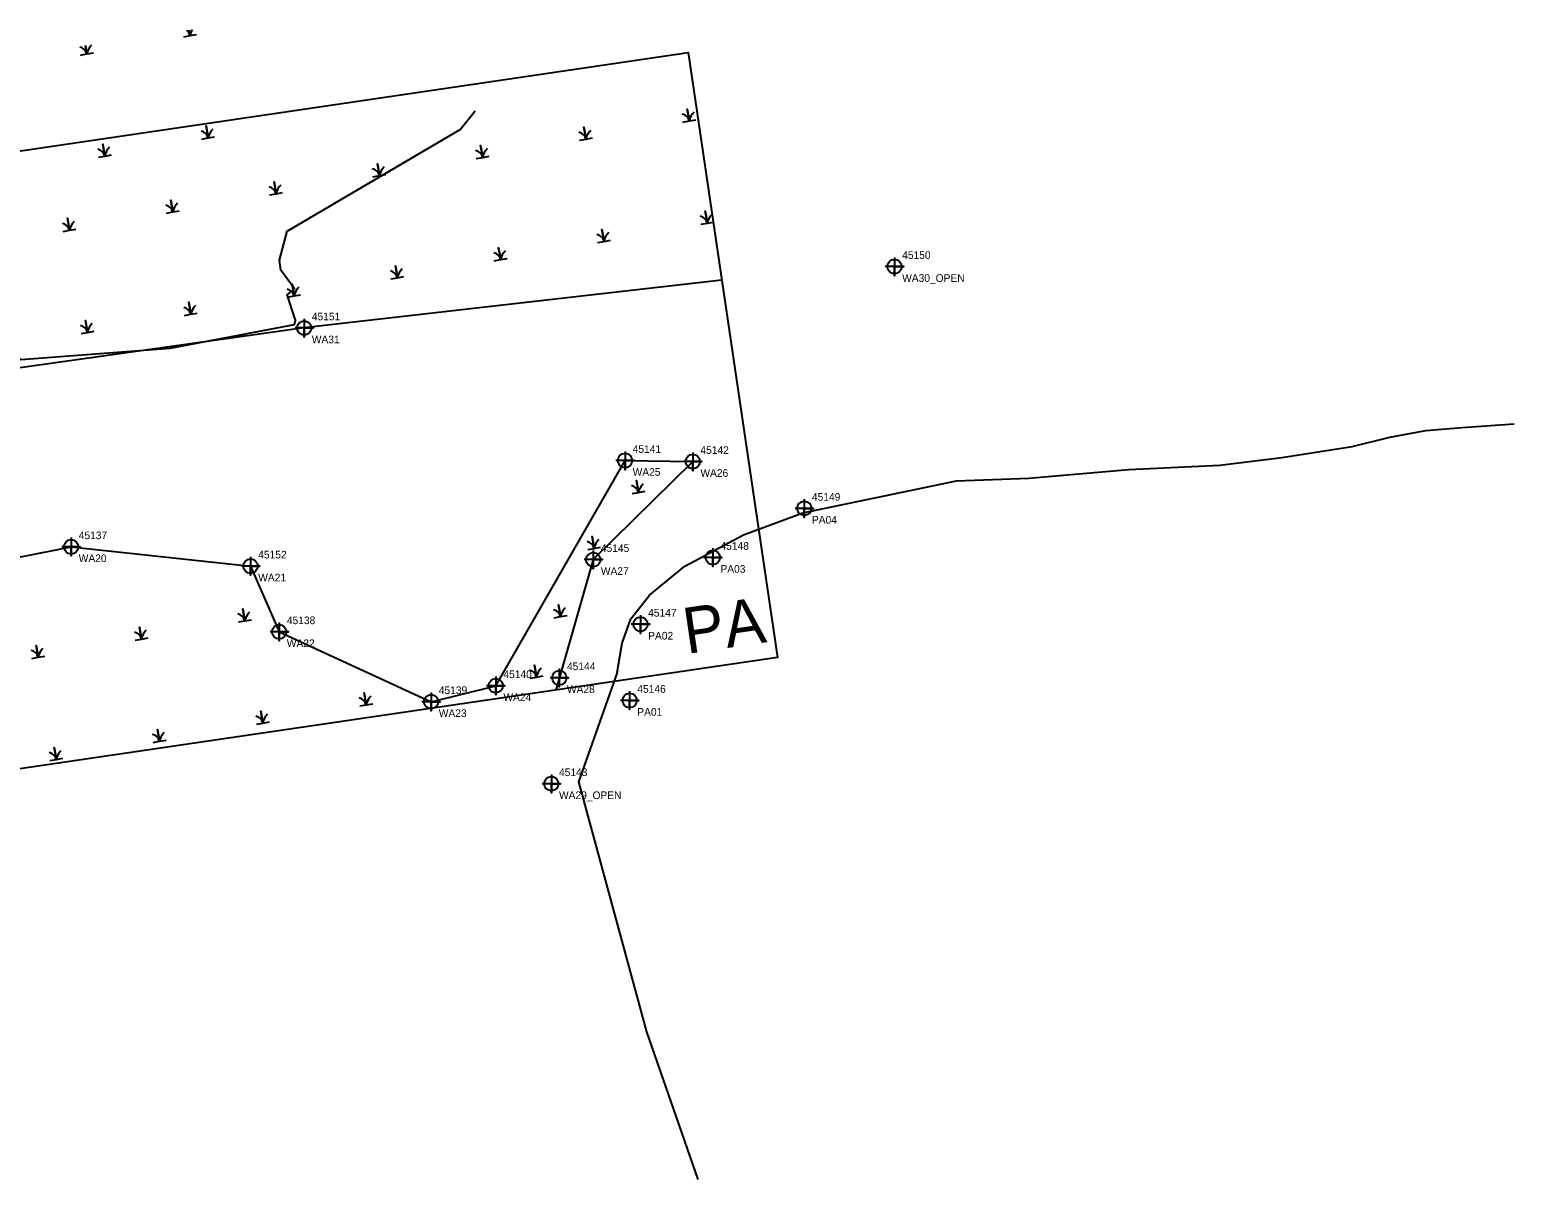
# Model space of a CAD drawing. Extents: x 2111078 to 2112839, y 581517 to 581907.
# Drawn here: x 2112353.6 to 2112839.1, y 581523.2 to 581906.7 of the extents above; entities that cross this region are included whole.
import ezdxf

# ---------------------------------------------------------------- set-up
doc = ezdxf.new("R2010")
doc.units = 0
for name, color, linetype in [('Default', 7, 'Continuous'), ('Exist Environmental Wetland Boundary', 7, 'Continuous'), ('Exist Environmental Wetland Boundary Cogo Comment', 7, 'Continuous'), ('Exist Environmental Wetland Boundary Cogo Number', 7, 'Continuous'), ('Exist Environmental Wetland Boundary Cogo Point CELL', 7, 'Continuous'), ('Exist Hydro Jurisdictional Stream or Body of Water Mitigable', 7, 'Continuous'), ('Exist Hydro Jurisdictional Stream or Body of Water Mitigable Cogo Comment', 7, 'Continuous'), ('Exist Hydro Jurisdictional Stream or Body of Water Mitigable Cogo Number', 7, 'Continuous'), ('Exist Hydro Jurisdictional Stream or Body of Water Mitigable Cogo Point CELL', 7, 'Continuous'), ('Exist Hydro Jurisdictional Stream or Body of Water Mitigable Text', 7, 'Continuous'), ('Exist Hydro Jurisdictional Stream or Body of Water NEU NonMitigable', 7, 'Continuous'), ('Exist Hydro Swamp or Marsh', 7, 'Continuous')]:
    doc.layers.add(name, color=color, linetype=linetype)

msp = doc.modelspace()

# ---------------------------------------------------------------- linework, layer by layer
at = {"layer": 'Default'}
msp.add_lwpolyline([(2111089.87, 581523.16), (2111077.52, 581722.78), (2111579.66, 581753.48), (2112568.99, 581899.18), (2112598.13, 581701.32), (2111600.4, 581554.74), (2111516.52, 581549.55)], close=True, dxfattribs=at)
at = {"layer": 'Exist Environmental Wetland Boundary'}
msp.add_lwpolyline([(2112579.95, 581824.73), (2112443.39, 581809.13), (2112256.64, 581782.86), (2112109, 581759.83), (2112105.64, 581760.42), (2112101.13, 581745.95), (2112105.09, 581733.68), (2112106.09, 581733.21), (2112105.61, 581730.22), (2112107.23, 581715.72), (2112118.04, 581694.33), (2112231.63, 581710.61), (2112367.17, 581737.55), (2112425.86, 581731.24), (2112435.22, 581709.75), (2112484.9, 581686.89), (2112506.03, 581692.11), (2112548.3, 581765.77), (2112570.44, 581765.42), (2112537.9, 581733.37), (2112525.65, 581690.67)], dxfattribs=at)
at = {"layer": 'Exist Environmental Wetland Boundary Cogo Point CELL'}
for points in [[(2112636.41, 581832.2), (2112636.41, 581826.2), (2112636.41, 581829.2), (2112639.41, 581829.2), (2112633.41, 581829.2)], [(2112443.39, 581812.12), (2112443.39, 581806.12), (2112443.39, 581809.12), (2112446.39, 581809.12), (2112440.39, 581809.12)], [(2112548.29, 581768.77), (2112548.29, 581762.77), (2112548.29, 581765.77), (2112551.29, 581765.77), (2112545.29, 581765.77)], [(2112570.44, 581768.42), (2112570.44, 581762.42), (2112570.44, 581765.42), (2112573.44, 581765.42), (2112567.44, 581765.42)], [(2112367.17, 581740.55), (2112367.17, 581734.55), (2112367.17, 581737.55), (2112370.17, 581737.55), (2112364.17, 581737.55)], [(2112425.86, 581734.24), (2112425.86, 581728.24), (2112425.86, 581731.24), (2112428.86, 581731.24), (2112422.86, 581731.24)], [(2112537.9, 581736.36), (2112537.9, 581730.36), (2112537.9, 581733.36), (2112540.9, 581733.36), (2112534.9, 581733.36)], [(2112435.22, 581712.75), (2112435.22, 581706.75), (2112435.22, 581709.75), (2112438.22, 581709.75), (2112432.22, 581709.75)], [(2112526.81, 581697.71), (2112526.81, 581691.71), (2112526.81, 581694.71), (2112529.81, 581694.71), (2112523.81, 581694.71)], [(2112506.03, 581695.11), (2112506.03, 581689.11), (2112506.03, 581692.11), (2112509.03, 581692.11), (2112503.03, 581692.11)], [(2112484.9, 581689.89), (2112484.9, 581683.89), (2112484.9, 581686.89), (2112487.9, 581686.89), (2112481.9, 581686.89)], [(2112524.21, 581663.06), (2112524.21, 581657.06), (2112524.21, 581660.06), (2112527.21, 581660.06), (2112521.21, 581660.06)]]:
    msp.add_lwpolyline(points, dxfattribs=at)
for centre in [(2112636.41, 581829.2), (2112443.39, 581809.12), (2112548.29, 581765.77), (2112570.44, 581765.42), (2112367.17, 581737.55), (2112425.86, 581731.24), (2112537.9, 581733.36), (2112435.22, 581709.75), (2112506.03, 581692.11), (2112526.81, 581694.71), (2112484.9, 581686.89), (2112524.21, 581660.06)]:
    msp.add_circle(centre, 2.34, dxfattribs=at)
at = {"layer": 'Exist Hydro Jurisdictional Stream or Body of Water Mitigable'}
msp.add_lwpolyline([(2112100.23, 581748.26), (2112103.02, 581756.15), (2112105.64, 581760.42), (2112110.13, 581763.39), (2112118.12, 581767.86), (2112152.81, 581774.25), (2112200.61, 581786.03), (2112247.18, 581789.46), (2112301.01, 581801.47), (2112342.46, 581803.44), (2112346.85, 581801.19), (2112350.69, 581798.8), (2112399.61, 581802.48), (2112440.25, 581810.21), (2112440.58, 581811.7), (2112437.79, 581819.92), (2112440.2, 581821.93), (2112435.76, 581827.98), (2112435.27, 581831.28), (2112437.88, 581840.73), (2112494.44, 581874.08), (2112499.34, 581880.11)], dxfattribs=at)
at = {"layer": 'Exist Hydro Jurisdictional Stream or Body of Water Mitigable Cogo Point CELL'}
for points in [[(2112606.91, 581753.13), (2112606.91, 581747.13), (2112606.91, 581750.13), (2112609.91, 581750.13), (2112603.91, 581750.13)], [(2112577, 581737.07), (2112577, 581731.07), (2112577, 581734.07), (2112580, 581734.07), (2112574, 581734.07)], [(2112553.36, 581715.22), (2112553.36, 581709.22), (2112553.36, 581712.22), (2112556.36, 581712.22), (2112550.36, 581712.22)], [(2112549.81, 581690.31), (2112549.81, 581684.31), (2112549.81, 581687.31), (2112552.81, 581687.31), (2112546.81, 581687.31)]]:
    msp.add_lwpolyline(points, dxfattribs=at)
for centre in [(2112606.91, 581750.13), (2112577, 581734.07), (2112553.36, 581712.22), (2112549.81, 581687.31)]:
    msp.add_circle(centre, 2.34, dxfattribs=at)
at = {"layer": 'Exist Hydro Jurisdictional Stream or Body of Water NEU NonMitigable'}
for points in [[(2112656.68, 581759.08), (2112680.36, 581759.96), (2112713.04, 581762.87), (2112742.82, 581764.2), (2112763.01, 581766.73), (2112786.04, 581770.35), (2112798.35, 581773.41), (2112810.13, 581775.61), (2112822.02, 581776.57), (2112839.07, 581777.8)], [(2112545.78, 581696.43), (2112547.4, 581706.04), (2112550.17, 581714.04), (2112556.31, 581721.74), (2112567.84, 581731.22), (2112587.06, 581741.49), (2112606.48, 581748.69), (2112656.68, 581759.08)], [(2112545.78, 581696.43), (2112533.1, 581660.7), (2112555.35, 581578.88), (2112572.1, 581530.62)]]:
    msp.add_lwpolyline(points, dxfattribs=at)
at = {"layer": 'Exist Hydro Swamp or Marsh'}
for p, q in [((2112552.43, 581757.08), (2112552.43, 581757.08)), ((2112537.9, 581738.78), (2112537.9, 581738.78)), ((2112526.92, 581716.49), (2112526.92, 581716.49)), ((2112519.08, 581696.72), (2112519.08, 581696.72))]:
    msp.add_line(p, q, dxfattribs=at)
for points in [[(2112403.99, 581904.35), (2112406.11, 581904.72), (2112405.79, 581906.52)], [(2112405.79, 581906.52), (2112406.11, 581904.72), (2112408.23, 581905.09)], [(2112370.21, 581898.39), (2112372.33, 581898.76), (2112371.85, 581901.52)], [(2112371.85, 581901.52), (2112372.33, 581898.76), (2112374.45, 581899.14)], [(2112567.22, 581876.46), (2112569.33, 581876.83), (2112568.65, 581880.72), (2112569.33, 581876.83), (2112571.45, 581877.21)], [(2112409.89, 581870.92), (2112412.01, 581871.29), (2112411.32, 581875.18), (2112412.01, 581871.29), (2112414.12, 581871.66)], [(2112533.44, 581870.5), (2112535.56, 581870.88), (2112534.87, 581874.76), (2112535.56, 581870.88), (2112537.67, 581871.25)], [(2112376.11, 581864.96), (2112378.23, 581865.33), (2112377.54, 581869.22), (2112378.23, 581865.33), (2112380.34, 581865.71)], [(2112499.66, 581864.55), (2112501.78, 581864.92), (2112501.09, 581868.81), (2112501.78, 581864.92), (2112503.89, 581865.29)], [(2112465.88, 581858.59), (2112468, 581858.96), (2112467.31, 581862.85), (2112468, 581858.96), (2112470.11, 581859.34)], [(2112432.1, 581852.64), (2112434.22, 581853.01), (2112433.53, 581856.89), (2112434.22, 581853.01), (2112436.33, 581853.38)], [(2112398.32, 581846.68), (2112400.44, 581847.05), (2112399.75, 581850.94), (2112400.44, 581847.05), (2112402.55, 581847.43)], [(2112364.54, 581840.72), (2112366.66, 581841.1), (2112365.97, 581844.98), (2112366.66, 581841.1), (2112368.77, 581841.47)], [(2112573.11, 581843.03), (2112575.23, 581843.4), (2112574.54, 581847.29), (2112575.23, 581843.4), (2112577.15, 581843.74)], [(2112539.33, 581837.07), (2112541.45, 581837.45), (2112540.76, 581841.33), (2112541.45, 581837.45), (2112543.57, 581837.82)], [(2112505.55, 581831.12), (2112507.67, 581831.49), (2112506.98, 581835.38), (2112507.67, 581831.49), (2112509.79, 581831.87)], [(2112471.77, 581825.16), (2112473.89, 581825.54), (2112473.21, 581829.42), (2112473.89, 581825.54), (2112476.01, 581825.91)], [(2112437.99, 581819.21), (2112440.11, 581819.58), (2112439.43, 581823.46), (2112440.11, 581819.58), (2112442.23, 581819.95)], [(2112404.21, 581813.25), (2112406.33, 581813.62), (2112405.65, 581817.51), (2112406.33, 581813.62), (2112408.45, 581814)], [(2112370.43, 581807.29), (2112372.55, 581807.67), (2112371.87, 581811.55), (2112372.55, 581807.67), (2112374.67, 581808.04)], [(2112550.62, 581754.95), (2112552.74, 581755.32), (2112552.05, 581759.21), (2112552.74, 581755.32), (2112554.85, 581755.7)], [(2112536.09, 581736.65), (2112538.21, 581737.03), (2112537.53, 581740.91), (2112538.21, 581737.03), (2112540.33, 581737.4)], [(2112421.9, 581712.96), (2112424.01, 581713.33), (2112423.33, 581717.22), (2112424.01, 581713.33), (2112426.13, 581713.71)], [(2112525.11, 581714.37), (2112527.23, 581714.74), (2112526.55, 581718.62), (2112527.23, 581714.74), (2112529.35, 581715.11)], [(2112388.12, 581707), (2112390.23, 581707.38), (2112389.55, 581711.26), (2112390.23, 581707.38), (2112392.35, 581707.75)], [(2112354.34, 581701.05), (2112356.45, 581701.42), (2112355.77, 581705.31), (2112356.45, 581701.42), (2112358.57, 581701.8)], [(2112517.27, 581694.59), (2112519.39, 581694.96), (2112518.7, 581698.85), (2112519.39, 581694.96), (2112521.5, 581695.34)], [(2112461.57, 581685.49), (2112463.69, 581685.86), (2112463, 581689.75), (2112463.69, 581685.86), (2112465.81, 581686.23)], [(2112427.79, 581679.53), (2112429.91, 581679.91), (2112429.22, 581683.79), (2112429.91, 581679.91), (2112432.03, 581680.28)], [(2112394.01, 581673.58), (2112396.13, 581673.95), (2112395.44, 581677.83), (2112396.13, 581673.95), (2112398.25, 581674.32)], [(2112360.23, 581667.62), (2112362.35, 581667.99), (2112361.66, 581671.88), (2112362.35, 581667.99), (2112364.47, 581668.37)]]:
    msp.add_lwpolyline(points, dxfattribs=at)
for centre, radius, start, end in [((2112410.87, 581904.02), 4.81, 146.4858, 171.6222), ((2112377.09, 581898.06), 4.81, 132.1274, 171.6222), ((2112403.13, 581903.97), 3.07, 14.1403, 52.2834), ((2112369.35, 581898.01), 3.07, 14.1403, 77.535), ((2112566.35, 581876.08), 3.07, 14.1403, 77.535), ((2112574.09, 581876.13), 4.81, 132.1274, 171.6222), ((2112409.02, 581870.54), 3.07, 14.1403, 77.535), ((2112416.76, 581870.59), 4.81, 132.1274, 171.6222), ((2112532.57, 581870.13), 3.07, 14.1403, 77.535), ((2112540.31, 581870.18), 4.81, 132.1274, 171.6222), ((2112382.98, 581864.63), 4.81, 132.1274, 171.6222), ((2112506.53, 581864.22), 4.81, 132.1274, 171.6222), ((2112375.24, 581864.58), 3.07, 14.1403, 77.535), ((2112498.79, 581864.17), 3.07, 14.1403, 77.535), ((2112465.01, 581858.21), 3.07, 14.1403, 77.535), ((2112472.75, 581858.26), 4.81, 132.1274, 171.6222), ((2112431.23, 581852.26), 3.07, 14.1403, 77.535), ((2112438.97, 581852.31), 4.81, 132.1274, 171.6222), ((2112397.45, 581846.3), 3.07, 14.1403, 77.535), ((2112405.19, 581846.35), 4.81, 132.1274, 171.6222), ((2112363.68, 581840.34), 3.07, 14.1403, 77.535), ((2112371.41, 581840.4), 4.81, 132.1274, 171.6222), ((2112572.25, 581842.65), 3.07, 14.1403, 77.535), ((2112579.98, 581842.7), 4.81, 132.1274, 171.6222), ((2112538.47, 581836.7), 3.07, 14.1403, 77.535), ((2112546.2, 581836.75), 4.81, 132.1274, 171.6222), ((2112504.69, 581830.74), 3.07, 14.1403, 77.535), ((2112512.42, 581830.79), 4.81, 132.1274, 171.6222), ((2112470.91, 581824.78), 3.07, 14.1403, 77.535), ((2112478.64, 581824.84), 4.81, 132.1274, 171.6222), ((2112437.13, 581818.83), 3.07, 14.1403, 77.535), ((2112444.86, 581818.88), 4.81, 132.1274, 171.6222), ((2112403.35, 581812.87), 3.07, 14.1403, 77.535), ((2112411.09, 581812.92), 4.81, 132.1274, 171.6222), ((2112369.57, 581806.92), 3.07, 14.1403, 77.535), ((2112377.31, 581806.97), 4.81, 132.1274, 171.6222), ((2112549.75, 581754.57), 3.07, 14.1403, 77.535), ((2112557.49, 581754.62), 4.81, 132.1274, 171.6222), ((2112535.23, 581736.28), 3.07, 14.1403, 77.535), ((2112542.97, 581736.33), 4.81, 132.1274, 171.6222), ((2112531.98, 581714.04), 4.81, 132.1274, 171.6222), ((2112421.03, 581712.58), 3.07, 14.1403, 77.535), ((2112428.77, 581712.63), 4.81, 132.1274, 171.6222), ((2112524.25, 581713.99), 3.07, 14.1403, 77.535), ((2112387.25, 581706.63), 3.07, 14.1403, 77.535), ((2112394.99, 581706.68), 4.81, 132.1274, 171.6222), ((2112353.47, 581700.67), 3.07, 14.1403, 77.535), ((2112361.21, 581700.72), 4.81, 132.1274, 171.6222), ((2112524.14, 581694.26), 4.81, 132.1274, 171.6222), ((2112516.4, 581694.21), 3.07, 14.1403, 77.535), ((2112460.71, 581685.11), 3.07, 14.1403, 77.535), ((2112468.44, 581685.16), 4.81, 132.1274, 171.6222), ((2112426.93, 581679.15), 3.07, 14.1403, 77.535), ((2112434.66, 581679.21), 4.81, 132.1274, 171.6222), ((2112393.15, 581673.2), 3.07, 14.1403, 77.535), ((2112400.88, 581673.25), 4.81, 132.1274, 171.6222), ((2112359.37, 581667.24), 3.07, 14.1403, 77.535), ((2112367.1, 581667.29), 4.81, 132.1274, 171.6222)]:
    msp.add_arc(centre, radius, start, end, dxfattribs=at)

# ---------------------------------------------------------------- texts
at = {"layer": 'Exist Environmental Wetland Boundary Cogo Comment'}
for s, p in [('WA30_OPEN', (2112638.91, 581824.2)), ('WA31', (2112445.89, 581804.12)), ('WA25', (2112550.79, 581760.77)), ('WA26', (2112572.94, 581760.43)), ('WA20', (2112369.67, 581732.55)), ('WA21', (2112428.36, 581726.24)), ('WA27', (2112540.4, 581728.36)), ('WA22', (2112437.72, 581704.75)), ('WA24', (2112508.53, 581687.11)), ('WA28', (2112529.31, 581689.71)), ('WA23', (2112487.4, 581681.89)), ('WA29_OPEN', (2112526.71, 581655.06))]:
    msp.add_text(s, height=2.5, dxfattribs=at).set_placement(p)
at = {"layer": 'Exist Environmental Wetland Boundary Cogo Number'}
for s, p in [('45150', (2112638.91, 581831.7)), ('45151', (2112445.89, 581811.62)), ('45141', (2112550.79, 581768.27)), ('45142', (2112572.94, 581767.93)), ('45137', (2112369.67, 581740.05)), ('45145', (2112540.4, 581735.86)), ('45152', (2112428.36, 581733.74)), ('45138', (2112437.72, 581712.25)), ('45144', (2112529.31, 581697.21)), ('45140', (2112508.53, 581694.61)), ('45139', (2112487.4, 581689.39)), ('45143', (2112526.71, 581662.56))]:
    msp.add_text(s, height=2.5, dxfattribs=at).set_placement(p)
at = {"layer": 'Exist Hydro Jurisdictional Stream or Body of Water Mitigable Cogo Comment'}
for s, p in [('PA04', (2112609.41, 581745.13)), ('PA03', (2112579.5, 581729.07)), ('PA02', (2112555.86, 581707.22)), ('PA01', (2112552.31, 581682.31))]:
    msp.add_text(s, height=2.5, dxfattribs=at).set_placement(p)
at = {"layer": 'Exist Hydro Jurisdictional Stream or Body of Water Mitigable Cogo Number'}
for s, p in [('45149', (2112609.41, 581752.63)), ('45148', (2112579.5, 581736.57)), ('45147', (2112555.86, 581714.72)), ('45146', (2112552.31, 581689.81))]:
    msp.add_text(s, height=2.5, dxfattribs=at).set_placement(p)
at = {"layer": 'Exist Hydro Jurisdictional Stream or Body of Water Mitigable Text'}
msp.add_text('PA', height=15, rotation=8.3579, dxfattribs=at).set_placement((2112568.47, 581702.49))

doc.saveas('drawing.dxf')
